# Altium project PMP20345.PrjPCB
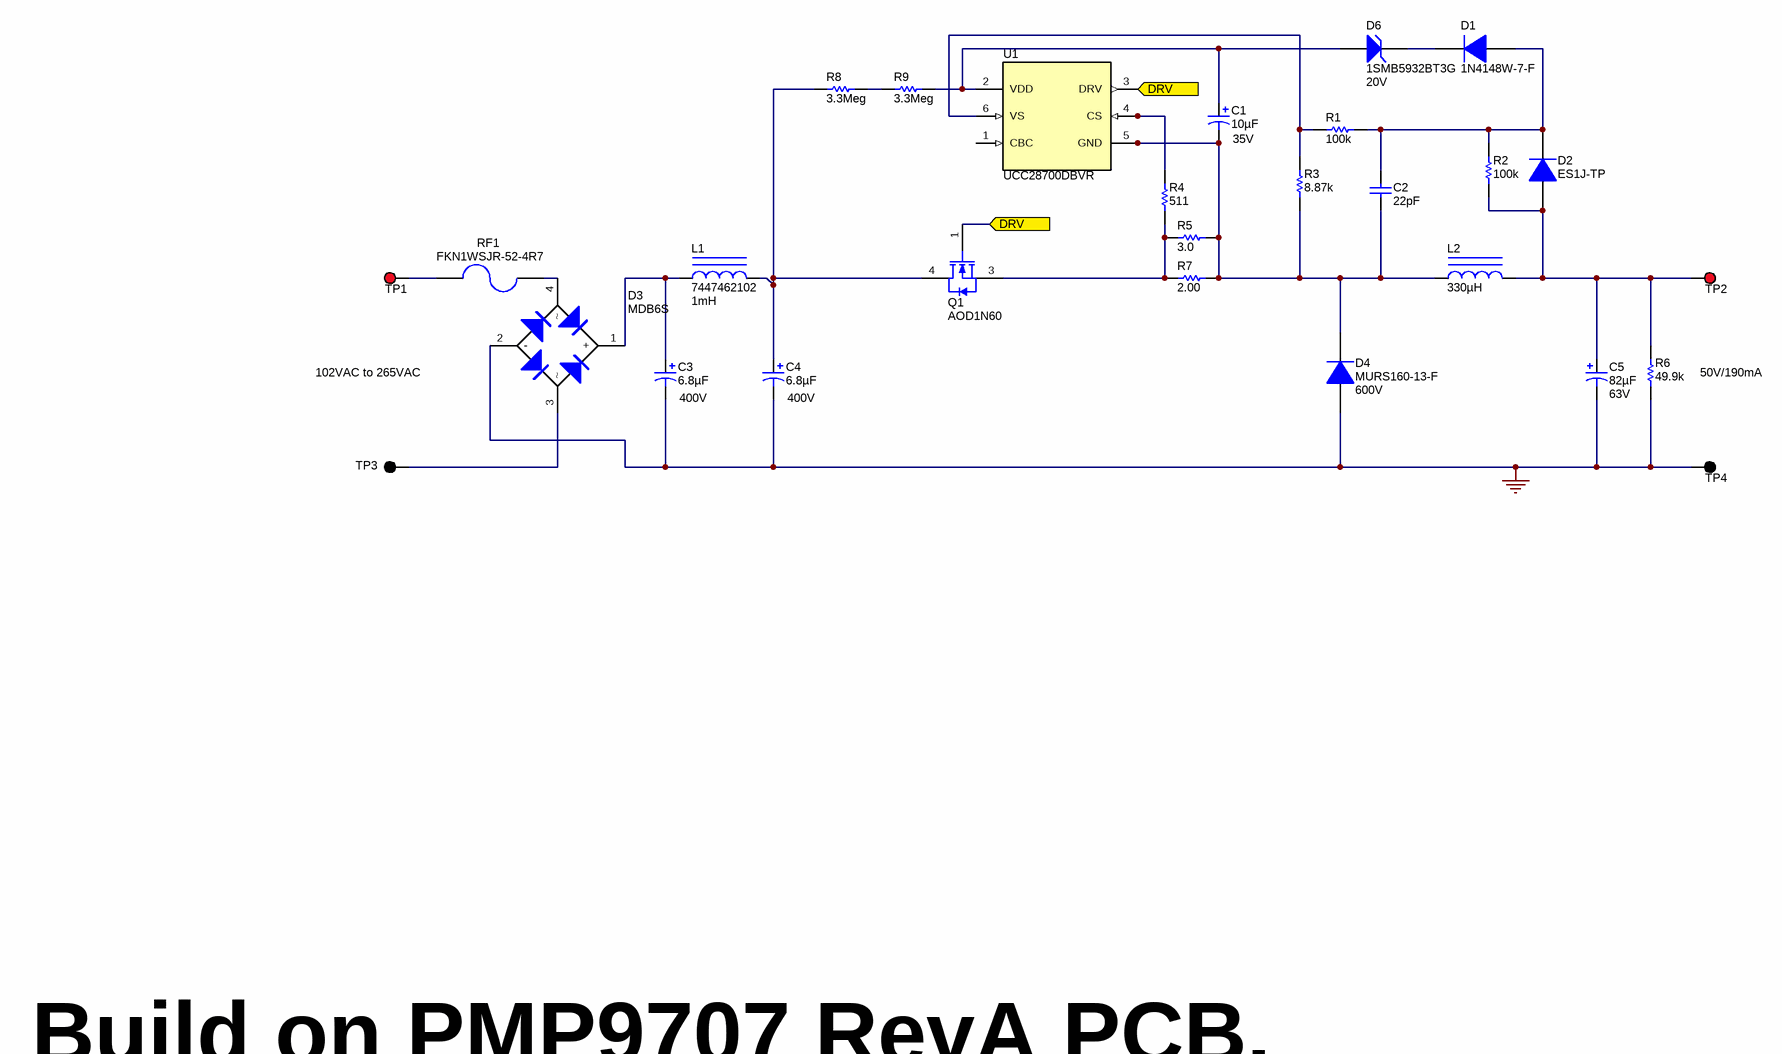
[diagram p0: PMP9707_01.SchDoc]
CopyrightYear: 2016; PCB_Layout: Sheng-Yang Yu; PCB_Rev: A; PRJ_Customer: Public Release; PRJ_Engineer: Adam Lin/Sheng-Yang Yu; PRJ_Number: PMP20345; PRJ_Title: UCC28700 High-side Buck Converter; SCH_Rev: B; TechSupport: http://www.ti.com/support
1 sheet, 28 parts. Net scope: flat (ports and power ports of the same name join across sheets).
Board file: PMP9707.PcbDoc

## Sheet PMP9707_01.SchDoc: 90Vac- 138Vac to 50V/0.19A
size 431 x 279 mm; Date: Not shown in title block; ApprovedBy: Not shown in title block; CheckedBy: Not shown in title block; Author: Not shown in title block; CompanyName: Not shown in title block; DrawnBy: Adam Lin; Engineer: Not shown in title block; Organization: Not shown in title block; Address1: Not shown in title block; Address2: Not shown in title block; Address3: Not shown in title block; Address4: Not shown in title block; DocumentNumber: 1; Revision: Use project parameter SCH_Rev; SheetNumber: 1; SheetTotal: 1; PageSetup: Record=PageOptions¦CenterHorizontal=True¦CenterVertical=True¦PrintScale=1.00¦XCorrection=1.00¦YCorrection=1.00¦PrintKind=0¦BorderSize=5000000¦LeftOffset=0¦BottomOffset=0¦Orientation=2¦PaperLength=1000¦PaperWidth=1000¦Scale=100¦PaperSource=15¦PrintQuality=600¦MediaType=1¦DitherType=10¦PaperKind=Letter¦PrintScaleMode=1

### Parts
C1  ValueDisplayed: 10µF  Value2: 35V  [CAPPR2-5x11]  (hidden comment: UVR1V100MDD1TA)
C2  ValueDisplayed: 22pF  [0603]  (hidden comment: 06035A220JAT2A)
C3  ValueDisplayed: 6.8µF  Value2: 400V  [CAPPRD350W60D800H1100]  (hidden comment: 400AX6R8M8x11)
C4  ValueDisplayed: 6.8µF  Value2: 400V  [CAPPRD350W60D800H1100]  (hidden comment: 400AX6R8M8x11)
C5  ValueDisplayed: 82µF  Value2: 63V  [PV_630x1100]  (hidden comment: UPV1E820MGD1TD)
D1  1N4148W-7-F  [SOD-123]
D2  ES1J-TP  [SMA]
D3  MDB6S  [MICRODIP_4]
D4  MURS160-13-F  value 600V  [SMB]
D6  1SMB5932BT3G  value 20V  [SMB]
L1  7447462102  ValueDisplayed: 1mH  [IND_WE-TI_XS]
L2  ValueDisplayed: 330µH  [WE_TI_1014]  (hidden comment: 7447480331)
Q1  AOD1N60  [DPAK]
R1  ValueDisplayed: 100k  [0603]  (hidden comment: RG1608P-104-B-T5)
R2  ValueDisplayed: 100k  [0603]  (hidden comment: RG1608P-104-B-T5)
R3  ValueDisplayed: 8.87k  [0603]  (hidden comment: RT0603BRD078K87L)
R4  value 511  [0603]  (hidden comment: CRCW0603511RFKEA)
R5  ValueDisplayed: 3.0  [2010]  (hidden comment: CRCW20103R00JNEF)
R6  ValueDisplayed: 49.9k  [2010]  (hidden comment: CRCW201049K9FKEF)
R7  ValueDisplayed: 2.00  [2010]  (hidden comment: CRCW20102R00FKEF)
R8  value 3.3Meg  [1206]  (hidden comment: CRCW12063M30JNEA)
R9  value 3.3Meg  [1206]  (hidden comment: CRCW12063M30JNEA)
RF1  FKN1WSJR-52-4R7  [RESAD1524W55L900D150]
TP1  5000  [Keystone5000]  (value not drawn)
TP2  5000  [Keystone5000]  (value not drawn)
TP3  5001  [Keystone5001]  (value not drawn)
TP4  5001  [Keystone5001]  (value not drawn)
U1  UCC28700DBVR  [DBV0006A_N]

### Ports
DRV

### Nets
GND: C3.2(-) C4.2(-) C5.2(-) D3.2(-) D4.2(A) R6.1 TP4.1
DRV: Q1.1(G) U1.3(DRV) ; port DRV
NetC1_1: C1.1(+) D6.2(A) R9.2 U1.2(VDD)
NetC1_2: C1.2(-) C2.2 D4.1(K) L2.1 R3.1 R5.2 R7.2 U1.5(GND)
NetC2_1: C2.1 D1.2(A) D2.1(K) R1.2 R2.2
NetC3_1: C3.1(+) D3.1(+) L1.1
NetC4_1: C4.1(+) L1.2 Q1.4(D) R8.1
NetC5_1: C5.1(+) D2.2(A) L2.2 R2.1 R6.2 TP2.1
NetD1_1: D1.1(K) D6.1(K)
NetD3_3: D3.3 TP3.1
NetD3_4: D3.4 RF1.1
NetQ1_3: Q1.3(S) R4.1 R5.1 R7.1
NetR1_1: R1.1 R3.2 U1.6(VS)
NetR4_2: R4.2 U1.4(CS)
NetR8_2: R8.2 R9.1
NetRF1_2: RF1.2 TP1.1

Not connected (* = marked no-connect by the designer): U1 1(CBC)

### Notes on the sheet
- 102VAC to 265VAC
- (near R6) 50V/190mA
- Build on PMP9707 RevA PCB.

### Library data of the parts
C1 = UVR1V100MDD1TA: CAP, AL, 10uF, 35V, +/-20%, TH; Manufacturer: Nichicon; Polarized: Y; CompType: Capacitor; U/M: EA; Cap_F: 0.00001; Tolerance_%: 20; Value1: Unknown; VDC_V: 35; TaMin_C: -40; TaMax_C: 85; Cap_Case: 5x11
C2 = 06035A220JAT2A: CAP, CERM, 22pF, 50V, +/-5%, C0G/NP0, 0603; Manufacturer: AVX; Polarized: N; CompType: Capacitor; U/M: EA; Cap_F: 0.000000000022; Tolerance_%: 5; ESR_Ohm: 0.259; Value1: 0.259 ohm; VDC_V: 50; TaMin_C: -55; TaMax_C: 125
C3 C4 = 400AX6R8M8x11: CAP, AL, 6.8uF, 400V, +/-20%, TH; Manufacturer: Rubycon; Polarized: Y; CompType: Capacitor; U/M: EA; Cap_F: 0.0000068; Tolerance_%: 20; Value1: Unknown; VDC_V: 400; TaMin_C: -40; TaMax_C: 105; Cap_Case: 8x11
C5 = UPV1E820MGD1TD: CAP, AL, 82 µF, 63 V, +/- 20%, 0.51 ohm, TH; Manufacturer: Nichicon; Polarized: Y; CompType: Capacitor; Value: 82uF; U/M: EA; Cap_F: 0.000082; Tolerance_%: 20; VDC_V: 63; ESR_ohm: 0.51; IRMS_A: 0.285; TaMin_C: -55; TaMax_C: 105; Cap_Case: 6.3x11mm; AEC Category: Q200
D1 = 1N4148W-7-F: Diode, Ultrafast, 100V, 0.15A, SOD-123; Manufacturer: Diodes Inc.; U/M: EA; Vf_V: 1.25; Value2: 1.25V; Io_A: 0.15; Vr_V: 100; TJmax_C: 150
D2 = ES1D-13-F: DIODE FAST REC 600V 1A DO214AC; Manufacturer: Diodes Inc.; U/M: EA; Io_A: 1; Vr_V: 600; TJmax_C: 150; RJC_CperW: 25; Type: Ultrafast
D3 = MDB6S: Diode, Switching-Bridge, 600 V, 1 A, MICRODIP_4; Manufacturer: Fairchild Semiconductor; U/M: EA; Vf_V: 1.1; Value: 600V; Value1: 1A; Value2: 1.1V; Io_A: 1; Vr_V: 600; TJmax_C: 150; AEC Category: Q101
D4 = MURS160-13-F: Diode, Ultrafast, 600V, 1A, SMB; Manufacturer: Diodes Inc.; U/M: EA; Vf_V: 1.25; Value2: 1.25V; Io_A: 1; Vr_V: 600; TJmax_C: 150; RJC_CperW: 13
D6 = 1SMB5932BT3G: Diode, Zener, 20 V, 550 mW, SMB; Manufacturer: ON Semiconductor; SymbolCreator: a0412235; U/M: EA; Power_W: 0.55; Vz_V: 20; Value1: 0.55W; RJA_CperW: 226; SizeAreaWB_mm2: 44.156; SizeArea_mm2: 21.336; SizeX_mm: 5.6; SizeY_mm: 3.81; SizeZ_mm: 2.6; AEC Category: Q101
L1 = 7447462102: Inductor, Unshielded Drum Core, Ferrite, 1mH, 0.25A, 4.38 ohm, TH; Manufacturer: Wurth Elektronik eiSos; Ind_H: 1.0E-3; Imax_A: 0.25; Irms: 0.25A @ 40C rise; Isat: 0.27A @ 10% inductance drop; DCR_ohm: 4.38; U/M: EA
L2 = 7447480331: Inductor, Wirewound, Ferrite, 330 µH, 1.4 A, 0.3 ohm, TH; Manufacturer: Wurth Elektronik; Value: 330uH; Ind_H: 330.0E-6; Imax_A: 1.4; Irms: 1.4A @ 40C rise; Isat: 1.6A @ 10% inductance drop; DCR_ohm: 0.3; Value1: 0.3 ohm; Value2: 1.4A; AEC Category: Q200; AEC Qualified: N
Q1 = AOD2N60: MOSFET N-CH 600V 1.3A TO252; Manufacturer: AOS; Alternate Manufacturer: None; U/M: EA; ChType: N; VdsMax_V: 600; Value1: ? ohm; Value2: 9.5 nC; QgTyp_nC: 9.5; Vgs_V: 30; IdsMax_A: 2; SizeAreaWB_mm2: 101.7114; SizeArea_mm2: 64.8114; SizeX_mm: 9.91; SizeY_mm: 6.54; SizeZ_mm: 2.29; AEC Category: Q101
R1 R2 = RG1608P-104-B-T5: RES, 100 k, 0.1%, 0.1 W, 0603; Manufacturer: Susumu Co Ltd; CompType: Resistor; Value: 100k; Res_ohm: 100000; Tolerance_%: 0.1; Value2: 0.1W; VDC_V: 75; TempCo: 25 ppm/C; SizeArea_mm2: 1.28; SizeX_mm: 1.6; SizeY_mm: 0.8; SizeZ_mm: 1; EIA_Code: E192; U/M: EA; AEC Category: Q200
R3 = RT0603BRD078K87L: RES, 8.87 k, 0.1%, 0.1 W, 0603; Manufacturer: Yageo America; CompType: Resistor; Value: 8.87k; Res_ohm: 8870; Value_Code: 8k87; Tolerance_%: 0.1; Value2: 0.1W; VDC_V: 75; TempCo: 25 ppm/C; SizeArea_mm2: 1.28; SizeX_mm: 1.6; SizeY_mm: 0.8; SizeZ_mm: 1; EIA_Code: E192; U/M: EA; AEC Category: Q200
R4 = CRCW0603511RFKEA: RES, 511 ohm, 1%, 0.1W, 0603; Manufacturer: Vishay-Dale; CompType: Resistor; Value_Code: 511R; Tolerance_%: 1; Power_W: 0.1; VDC_V: 75; TempCo: 100 ppm/C; EIA_Code: E96; U/M: EA
R5 = CRCW20103R00JNEF: RES, 3.0, 5%, 0.75 W, AEC-Q200 Grade 0, 2010; Manufacturer: Vishay-Dale; CompType: Resistor; Value: 3.0; Res_ohm: 3; Value_Code: 3R00; Tolerance_%: 5; Power_W: 0.75; Value2: 0.75W; VDC_V: 400; TempCo: 200 ppm/C; SizeArea_mm2: 12.5; SizeY_mm: 2.5; SizeZ_mm: 1.66; EIA_Code: E24; U/M: EA; AEC Category: Q200; AEC Qualified: Y; AEC Grade: 0
R6 = CRCW201049K9FKEF: RES, 49.9 k, 1%, 0.75 W, AEC-Q200 Grade 0, 2010; Manufacturer: Vishay-Dale; CompType: Resistor; Value: 49.9k; Res_ohm: 49900; Value_Code: 49k9; Tolerance_%: 1; Power_W: 0.75; Value2: 0.75W; VDC_V: 400; TempCo: 100 ppm/C; SizeArea_mm2: 12.5; SizeX_mm: 5; SizeY_mm: 2.5; SizeZ_mm: 1.66; EIA_Code: E96; U/M: EA; AEC Category: Q200; AEC Qualified: Y; AEC Grade: 0
R7 = CRCW20102R00FKEF: RES, 2.00, 1%, 0.75 W, AEC-Q200 Grade 0, 2010; Manufacturer: Vishay-Dale; CompType: Resistor; Value: 2.00; Res_ohm: 2; Value_Code: 2R00; Tolerance_%: 1; Power_W: 0.75; Value2: 0.75W; VDC_V: 400; TempCo: 100 ppm/C; SizeArea_mm2: 12.5; SizeX_mm: 5; SizeY_mm: 2.5; SizeZ_mm: 1.66; EIA_Code: E96; U/M: EA; AEC Category: Q200; AEC Qualified: Y; AEC Grade: 0
R8 R9 = CRCW12063M30JNEA: RES, 3.3Meg ohm, 5%, 0.25W, 1206; Manufacturer: Vishay-Dale; CompType: Resistor; Res_ohm: 3300000; Value_Code: 3M30; Tolerance_%: 5; Power_W: 0.25; VDC_V: 200; TempCo: 200 ppm/C; EIA_Code: E24; U/M: EA
RF1 = FKN1WSJR-52-4R7: RES, 4.7 ohm, 5%, 1W, Fusible, TH; Manufacturer: Yageo America; SymbolCreator: a0412235; CompType: Fusible Resistor; Res_ohm: 4.7; Value: 4.7; Value_Code: 4R70; Tolerance_%: 5; Power_W: 1; TempCo: 350 ppm/C; EIA_Code: E24; U/M: EA
TP1 TP2 = 5000: Test Point, Miniature, Red, TH; Manufacturer: Keystone; CompType: Test Point Loop; U/M: EA
TP3 TP4 = 5001: Test Point, TH, Miniature, Black; Manufacturer: Keystone; Alternate Manufacturer: Any; Alternate PartNumber: Equivalent; CompType: Test Point Loop; U/M: EA
U1 = UCC28700DBVR: Constant-Voltage, Constant-Current Controller With Primary-Side Regulation, DBV0006A; Alternate PartNumber: UCC28700DBVT; Manufacturer: Texas Instruments; SymbolCreator: a0799628; SizeArea_mm2: 8.12; SizeAreaWB_mm2: 14.82; SizeX_mm: 2.8; SizeY_mm: 2.9; SizeZ_mm: 1.45; CompType: IC; U/M: EA

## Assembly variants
001: not fitted Q1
